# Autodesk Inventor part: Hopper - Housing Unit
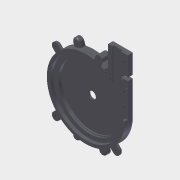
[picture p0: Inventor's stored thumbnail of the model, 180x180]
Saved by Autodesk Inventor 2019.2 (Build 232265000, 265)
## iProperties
Created: 2005-11
Part Number: Hopper - Housing Unit
Document SubType Name: Modeling
Designer: floress
Material: Default
Density: 1 g/cm^3
Appearance: Steel - Polished
Author: floress
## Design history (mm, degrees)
sketch "Sketch1"
  geometry: L1 (88.9, 0)-(88.9, 108.888); L2 (88.9, 108.888)-(50.151, 108.888); L3 (50.151, 108.888)-(50.151, 66.361); L4 (-6.173, 81.933)-(-3.468, 74.465); L5 (-19.921, 76.953)-(-17.403, 70.002); L6 (12.7, 0)-(12.7, 49.458); L7 (31.573, 81.933)-(28.868, 74.465); L8 (45.321, 76.953)-(42.803, 70.002); L9 (12.7, 0)-(58.572, 0); L10 (-6.173, -81.933)-(-3.468, -74.465); L11 (-19.921, -76.953)-(-17.403, -70.002); L12 (31.573, -81.933)-(28.868, -74.465); L13 (45.321, -76.953)-(42.803, -70.002); C1 r 6.35 at (12.7, 0) reference; A1 r 7.311 centre (-13.047, 79.443) between (-6.173, 81.933) and (-19.921, 76.953); A2 r 7.311 centre (38.447, 79.443) between (45.321, 76.953) and (31.573, 81.933); A3 r 7.311 centre (-13.047, -79.443) between (-19.921, -76.953) and (-6.173, -81.933); A4 r 7.311 centre (38.447, -79.443) between (31.573, -81.933) and (45.321, -76.953); A5 r 76.2 centre (12.7, 0) between (50.151, 66.361) and (42.803, 70.002); A6 r 76.2 centre (12.7, 0) between (28.868, 74.465) and (-3.468, 74.465); A7 r 76.2 centre (12.7, 0) between (-17.403, 70.002) and (-17.403, -70.002); A8 r 76.2 centre (12.7, 0) between (-3.468, -74.465) and (28.868, -74.465); A9 r 76.2 centre (12.7, 0) between (42.803, -70.002) and (88.9, 0)
  constraints: 26 end point, 18 point on circle, 15 symmetric about line, 9 centre point, 3 tangent, 2 parallel, 2 perpendicular, 1 coincident, 1 vertical, 3 other
extrude "Extrusion1" new body sketch "Sketch1" distance "d1" = 9.525; taper "d2" = 0 deg
sketch "Sketch2"
  geometry: L1 (-46.351, 59.051)-(71.751, 59.051); L2 (71.751, 59.051)-(71.751, -59.051); L3 (71.751, -59.051)-(-46.351, -59.051); L4 (-46.351, -59.051)-(-46.351, 59.051); L5 (-41.182, 64.221)-(-35.763, 58.803); L6 (-46.351, 59.051)-(-41.182, 53.882); L7 (-51.521, 53.882)-(-46.103, 48.463); L8 (12.7, 0)-(-20.66, 0); L9 (-51.521, -53.882)-(-46.103, -48.463); L10 (-41.182, -64.221)-(-35.763, -58.803); L11 (12.7, 0)-(12.7, -18.977); L12 (66.582, -64.221)-(61.163, -58.803); L13 (76.921, -53.882)-(71.503, -48.463); L14 (50.151, 66.361)-(50.151, 108.888) reference; L15 (47.03, 60.831)-(50.151, 66.361) reference; L16 (82.55, 0)-(88.9, 0) reference; L17 (45.321, 76.953)-(42.803, 70.002) reference; L18 (28.868, 74.465)-(31.573, 81.933) reference; L19 (42.803, 70.002)-(45.321, 76.953); L20 (28.868, 74.465)-(31.573, 81.933); A1 r 76.2 centre (12.7, 0) between (42.803, -70.002) and (88.9, 0) reference; A2 r 76.2 centre (12.7, 0) between (-17.403, 70.002) and (-17.403, -70.002) reference; A3 r 76.2 centre (12.7, 0) between (-3.468, -74.465) and (28.868, -74.465) reference; A4 r 7.311 centre (-46.351, 59.051) between (-41.182, 64.221) and (-51.521, 53.882); A5 r 7.311 centre (-46.351, -59.051) between (-51.521, -53.882) and (-41.182, -64.221); A6 r 7.311 centre (71.751, -59.051) between (66.582, -64.221) and (76.921, -53.882); A7 r 76.2 centre (12.7, 0) between (-46.103, 48.463) and (-46.103, -48.463); A8 r 76.2 centre (12.7, 0) between (-35.763, -58.803) and (61.163, -58.803); A9 r 76.2 centre (12.7, 0) between (28.868, 74.465) and (-3.468, 74.465) reference; A10 r 69.85 centre (12.7, 0) between (44.353, 62.266) and (82.484, -3.037); A11 r 76.2 centre (12.7, 0) between (50.151, 66.361) and (42.803, 70.002) reference; A12 r 3.175 centre (45.792, 65.097) between (44.353, 62.266) and (47.231, 67.927); A13 r 3.175 centre (85.656, -3.175) between (88.828, -3.313) and (82.484, -3.037); A14 r 76.2 centre (12.7, 0) between (71.503, -48.463) and (88.828, -3.313); A15 r 76.2 centre (12.7, 0) between (47.231, 67.927) and (42.803, 70.002); A16 r 76.2 centre (12.7, 0) between (28.868, 74.465) and (-35.763, 58.803); A17 r 7.311 centre (38.447, 79.443) between (45.321, 76.953) and (31.573, 81.933) reference; A18 r 7.311 centre (38.447, 79.443) between (45.321, 76.953) and (31.573, 81.933); 3 further points
  constraints: 36 end point, 27 point on circle, 12 centre point, 10 symmetric about line, 10 tangent, 4 perpendicular, 3 coincident, 3 equal length, 3 equal radius, 3 midpoint, 2 collinear, 2 horizontal alignment, 1 horizontal, 1 vertical alignment, 1 other
  dimensions: "d7" = 6.35 radial gap between concentric circles of A2 A10
extrude "Extrusion2" join sketch "Sketch2" distance "d5" = 6.35; taper "d6" = 0 deg
sketch "Sketch3"
  geometry: L1 (50.151, 108.888)-(88.9, 108.888) reference; L2 (58.492, 108.888)-(75.073, 108.888); L3 (58.492, 46.79)-(58.492, 108.888); L4 (75.073, 108.888)-(75.073, 0); L5 (58.492, 46.79)-(50.776, 46.79); A1 r 69.85 centre (12.7, 0) between (44.353, 62.266) and (82.484, -3.037) reference; A2 r 3.175 centre (45.792, 65.097) between (44.353, 62.266) and (47.231, 67.927) reference; A3 r 61.349 centre (13.724, 0) between (-47.625, 0) and (75.073, 0); A4 r 60.325 centre (12.7, 0) between (50.776, 46.79) and (-47.625, 0); A5 r 60.325 centre (12.7, 0) between (73.025, -0.053) and (73.025, 0.053)
  constraints: 9 end point, 6 point on circle, 3 centre point, 2 point on line, 1 coincident, 1 horizontal, 1 perpendicular, 1 tangent
extrude "Extrusion3" cut sketch "Sketch3" distance "d9" = 6.35; taper "d10" = 0 deg
sketch "Sketch4"
  geometry: L1 (75.073, 108.888)-(88.9, 108.888) reference; L2 (50.776, 46.79)-(58.492, 46.79) reference; L3 (66.596, -31.117)-(73.192, -34.925); L4 (12.7, -61.341)-(12.7, -69.85); L5 (50.151, 108.888)-(50.151, 66.361) reference; L6 (43.627, -53.568)-(47.625, -60.492); L7 (75.073, 0)-(82.55, 0); L8 (12.7, 0)-(-1.927, 0); C1 r 1.422 at (54.634, 59.173); C2 r 1.422 at (54.634, 51.553); C3 r 1.74 at (81.987, 93.013); C4 r 1.74 at (81.987, 67.613); C5 r 1.74 at (81.987, 42.213); C6 r 1.74 at (81.987, 16.813); C7 r 1.422 at (69.894, -33.021); C8 r 1.422 at (45.721, -57.194); C9 r 1.593 at (12.7, -66.042); C10 r 1.422 at (78.742, 0); C11 r 1.593 at (12.7, 66.042); C12 r 1.422 at (45.721, 57.194); A1 r 69.85 centre (12.7, 0) between (44.353, 62.266) and (82.484, -3.037) reference; A2 r 76.2 centre (12.7, 0) between (-17.403, -70.002) and (-3.468, -74.465) reference; A3 r 61.349 centre (13.724, 0) between (-47.625, 0) and (75.073, 0) reference; A4 r 66.042 centre (12.7, 0) between (69.894, -33.021) and (45.721, -57.194); 3 further points
  constraints: 13 centre point, 11 point on circle, 10 end point, 7 equal radius, 6 vertical alignment, 4 midpoint, 3 point on line, 2 symmetric about line, 1 coincident, 1 parallel, 1 perpendicular, 2 other
  dimensions: "d13" = 2.8448 diameter of C1; "d14" = 7.62 distance of C2.centre C1.centre; "d15" = 4.7625 distance of point (54.634, 46.79) C2.centre; "d16" = 3.4798 diameter of C3; "d17" = 25.4 distance of C5.centre C6.centre; "d18" = 25.4 distance of C4.centre C5.centre; "d19" = 25.4 distance of C4.centre C3.centre; "d20" = 15.875 distance of point (81.987, 108.888) C3.centre; "d39" = 30 deg angle of L6 L4; "d40" = 30 deg angle of L3 L6; "d41" = 30 deg angle of L7 L3
extrude "Extrusion4" cut sketch "Sketch4" distance "d21" = 6.35; taper "d22" = 0 deg
thread "Thread1" dims "d23" = 25.4, "d24" = 0
thread "Thread2" dims "d25" = 25.4, "d26" = 0
thread "Thread3" dims "d27" = 25.4, "d28" = 0
thread "Thread4" dims "d29" = 25.4, "d30" = 0
thread "Thread5" dims "d31" = 25.4, "d32" = 0
thread "Thread6" dims "d33" = 25.4, "d34" = 0
sketch "Sketch5"
  geometry: C1 r 7.144 at (12.7, 0); A1 r 60.325 centre (12.7, 0) between (50.776, 46.79) and (-47.625, 0) reference
  constraints: 1 centre point, 1 coincident
  dimensions: "d36" = 14.2875 diameter of C1
extrude "Extrusion5" cut sketch "Sketch5" distance "d37" = 6.35; taper "d38" = 0 deg
thread "Thread7" dims "d42" = 25.4, "d43" = 0
thread "Thread8" dims "d44" = 25.4, "d45" = 0
thread "Thread9" dims "d46" = 25.4, "d47" = 0
thread "Thread10" dims "d48" = 25.4, "d49" = 0
thread "Thread11" dims "d50" = 25.4, "d51" = 0
thread "Thread12" dims "d52" = 25.4, "d53" = 0
sketch "Sketch6"
  geometry: L1 (58.492, 46.79)-(50.776, 46.79) reference; L2 (75.073, 0)-(75.073, 108.888) reference; L3 (58.492, 108.888)-(75.073, 108.888) reference; L4 (58.492, 108.888)-(58.492, 46.79) reference; A1 r 60.325 centre (12.7, 0) between (50.776, 46.79) and (-47.625, 0) reference; A2 r 61.349 centre (13.724, 0) between (-47.625, 0) and (75.073, 0) reference; A3 r 60.325 centre (12.7, 0) between (-47.625, 0) and (50.776, 46.79)
  constraints: 4 point on circle, 1 centre point, 1 coincident
extrude "Extrusion6" join sketch "Sketch6" distance "d54" = 3.175; taper "d55" = 0 deg
fillet "Fillet1" dims "d56" = 3.175
hole "Hole1" diameter "d59" = 3.302; stored, may be unused: countersink angle "d63" = 90 deg, drill point angle "d65" = 118 deg; dims "d57" = 25.4, "d58" = 25.4, "d60" = 12.7, "d61" = 3.6068, "d62" = 6.35, "d64" = 6.35
hole "Hole2" diameter "d68" = 3.302; stored, may be unused: countersink angle "d72" = 90 deg, drill point angle "d74" = 118 deg; dims "d66" = 25.4, "d67" = 25.4, "d69" = 12.7, "d70" = 3.6068, "d71" = 6.35, "d73" = 6.35
hole "Hole3" diameter "d77" = 3.302; stored, may be unused: countersink angle "d81" = 90 deg, drill point angle "d83" = 118 deg; dims "d75" = 25.4, "d76" = 25.4, "d78" = 12.7, "d79" = 3.6068, "d80" = 6.35, "d82" = 6.35
hole "Hole4" diameter "d86" = 3.302; stored, may be unused: countersink angle "d90" = 90 deg, drill point angle "d92" = 118 deg; dims "d84" = 25.4, "d85" = 25.4, "d87" = 12.7, "d88" = 3.6068, "d89" = 6.35, "d91" = 6.35
hole "Hole5" diameter "d95" = 3.302; stored, may be unused: countersink angle "d99" = 90 deg, drill point angle "d101" = 118 deg; dims "d93" = 25.4, "d94" = 25.4, "d96" = 12.7, "d97" = 3.6068, "d98" = 6.35, "d100" = 6.35
hole "Hole6" diameter "d104" = 3.302; stored, may be unused: countersink angle "d108" = 90 deg, drill point angle "d110" = 118 deg; dims "d102" = 25.4, "d103" = 25.4, "d105" = 12.7, "d106" = 3.6068, "d107" = 6.35, "d109" = 15.875
hole "Hole7" diameter "d113" = 3.302; stored, may be unused: countersink angle "d117" = 90 deg, drill point angle "d119" = 118 deg; dims "d111" = 25.4, "d112" = 25.4, "d114" = 12.7, "d115" = 3.6068, "d116" = 6.35, "d118" = 6.35
sketch "Sketch7"
  geometry: L1 (-25.816, -53.992)-(-66.692, 13.116); L2 (-66.692, 13.116)-(0.416, 53.992); L3 (-25.816, -53.992)-(41.292, -13.116); L4 (41.292, -13.116)-(0.416, 53.992); L5 (-12.7, 0)-(-33.591, 11.416) reference; C1 r 1.74 at (-66.692, 13.116); C2 r 1.74 at (0.416, 53.992); C3 r 1.74 at (41.292, -13.116); C4 r 1.74 at (-25.816, -53.992); A1 r 76.2 centre (-12.7, 0) between (-42.803, 70.002) and (-50.151, 66.361) reference; A2 r 55.562 centre (-12.7, 0) between (-66.692, 13.116) and (0.416, 53.992); A3 r 76.2 centre (-12.7, 0) between (3.468, 74.465) and (-28.868, 74.465) reference
  constraints: 10 end point, 5 centre point, 3 equal radius, 3 perpendicular, 3 point on circle, 1 coincident, 1 parallel, 1 other
  dimensions: "d120" = 111.125 diameter of A2; "d121" = 3.4798 diameter of C1; "d131" = 30 deg angle of L1 L5
hole "Hole8" sketch "Sketch7" diameter "d122" = 2.6416; stored, may be unused: countersink angle "d126" = 82 deg, drill point angle "d128" = 118 deg; dims "d123" = 12.7, "d124" = 9.525, "d125" = 6.35, "d127" = 2.54
sketch "Sketch8"
  geometry: L1 (-88.9, 0)-(-88.9, 108.888) reference; L2 (-88.9, 108.888)-(-50.151, 108.888) reference; L3 (-75.073, 108.888)-(-75.073, 0) reference; L4 (-88.9, 71.232)-(-88.9, 64.757); C1 r 1.422 at (-85.725, 51.738); A1 r 3.175 centre (-75.073, 64.438) between (-77.114, 62.005) and (-73.033, 66.871); A2 r 19.75 centre (-85.725, 51.738) between (-73.033, 66.871) and (-88.9, 71.232); A3 r 13.4 centre (-85.725, 51.738) between (-77.114, 62.005) and (-88.9, 64.757)
  constraints: 6 point on circle, 4 centre point, 3 point on line, 2 coincident, 2 end point, 2 tangent, 1 parallel
  dimensions: "d129" = 6.35 diameter of A1; "d132" = 44.45 distance from line of A1.centre L2; "d133" = 2.8448 diameter of C1; "d134" = 3.175 distance from line of L1 C1.centre; "d135" = 12.7 vertical distance of A1.centre C1.centre
extrude "Extrusion7" cut sketch "Sketch8" extent not by distance; stored distance "d136" = 25.4; taper "d137" = 0 deg
sketch "Sketch9"
  geometry: C1 r 1.422 at (-85.725, 51.738) reference; C2 r 2.216 at (-85.725, 51.738); A1 r 19.75 centre (-85.725, 51.738) between (-73.033, 66.871) and (-88.9, 71.232) reference
  constraints: 1 centre point, 1 coincident
  dimensions: "d140" = 0.79375 radial gap between concentric circles of C2 C1
extrude "Extrusion8" join sketch "Sketch9" distance "d138" = 0.79375; taper "d139" = 0 deg
sketch "Sketch10"
  geometry: L1 (-88.9, 0)-(-88.9, 64.757); L2 (-45.321, -76.953)-(-42.803, -70.002); L3 (-28.868, -74.465)-(-31.573, -81.933); L4 (6.173, -81.933)-(3.468, -74.465); L5 (17.403, -70.002)-(19.921, -76.953); L6 (19.921, 76.953)-(17.403, 70.002); L7 (3.468, 74.465)-(6.173, 81.933); L8 (-31.573, 81.933)-(-28.868, 74.465); L9 (-42.803, 70.002)-(-45.321, 76.953); L10 (-50.151, 108.888)-(-50.151, 66.361); L11 (-88.9, 108.888)-(-50.151, 108.888); L12 (-88.9, 71.232)-(-88.9, 108.888); L13 (-66.582, -64.221)-(-61.163, -58.803) reference; L14 (-71.503, -48.463)-(-76.921, -53.882) reference; L15 (35.763, -58.803)-(41.182, -64.221) reference; L16 (51.521, -53.882)-(46.103, -48.463) reference; L17 (46.103, 48.463)-(51.521, 53.882) reference; L18 (41.182, 64.221)-(35.763, 58.803) reference; C1 r 1.321 at (41.292, -13.116); C2 r 1.321 at (0.416, 53.992); C3 r 1.321 at (-66.692, 13.116); C4 r 1.321 at (-25.816, -53.992); C5 r 1.651 at (-38.447, 79.443); C6 r 1.651 at (13.047, 79.443); C7 r 1.651 at (13.047, -79.443); C8 r 1.651 at (-38.447, -79.443); C9 r 7.144 at (-12.7, 0); C10 r 1.422 at (-85.725, 51.738) reference; C11 r 1.651 at (46.351, -59.051) reference; C12 r 1.651 at (-71.751, -59.051) reference; C13 r 1.651 at (46.351, 59.051) reference; A1 r 13.4 centre (-85.725, 51.738) between (-77.114, 62.005) and (-88.9, 64.757); A2 r 7.311 centre (-38.447, -79.443) between (-45.321, -76.953) and (-31.573, -81.933); A3 r 76.2 centre (-12.7, 0) between (-28.868, -74.465) and (3.468, -74.465); A4 r 7.311 centre (13.047, -79.443) between (6.173, -81.933) and (19.921, -76.953); A5 r 7.311 centre (13.047, 79.443) between (19.921, 76.953) and (6.173, 81.933); A6 r 76.2 centre (-12.7, 0) between (3.468, 74.465) and (-28.868, 74.465); A7 r 7.311 centre (-38.447, 79.443) between (-31.573, 81.933) and (-45.321, 76.953); A8 r 76.2 centre (-12.7, 0) between (-42.803, 70.002) and (-50.151, 66.361); A9 r 19.75 centre (-85.725, 51.738) between (-73.033, 66.871) and (-88.9, 71.232); A10 r 3.175 centre (-75.073, 64.438) between (-77.114, 62.005) and (-73.033, 66.871); A11 r 7.311 centre (-71.751, -59.051) between (-76.921, -53.882) and (-66.582, -64.221) reference; A12 r 7.311 centre (46.351, -59.051) between (41.182, -64.221) and (51.521, -53.882) reference; A13 r 7.311 centre (46.351, 59.051) between (51.521, 53.882) and (41.182, 64.221) reference; A14 r 76.2 centre (-12.7, 0) between (35.763, 58.803) and (17.403, 70.002); A15 r 76.2 centre (-12.7, 0) between (17.403, -70.002) and (35.763, -58.803); A16 r 76.2 centre (-12.7, 0) between (46.103, -48.463) and (46.103, 48.463); A17 r 76.2 centre (-12.7, 0) between (-88.9, 0) and (-71.503, -48.463); A18 r 76.2 centre (-12.7, 0) between (-61.163, -58.803) and (-42.803, -70.002); 1 further point
  constraints: 30 end point, 30 point on circle, 24 centre point
body "Solid1"
node "Reference1"
other parameters: "d0" = 152.4, "NestingThickness" = 16.6624
